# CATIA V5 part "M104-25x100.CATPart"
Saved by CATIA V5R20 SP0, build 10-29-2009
Part number: M104-25x100
Source: Unknown
Bounding box of the stored display mesh (mm): x -12.497 to 12.497, y -12.358 to 12.358, z 0 to 100
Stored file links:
  C:\Users\Utente\Desktop\IO LAVORO\3D X SITO CF\X SITO\M104\M104-25x100.CATPart
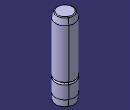
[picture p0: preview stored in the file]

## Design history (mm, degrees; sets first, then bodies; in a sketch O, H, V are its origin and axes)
Body1 (main body)
  Solid1 "PartBody": solid without history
